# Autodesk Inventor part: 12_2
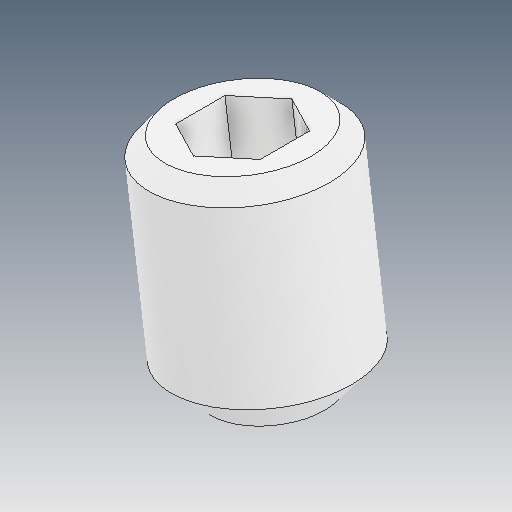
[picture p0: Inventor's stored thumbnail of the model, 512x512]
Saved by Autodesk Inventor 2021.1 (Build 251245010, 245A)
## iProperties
Created: 2021-06
Part Number: 12_2
Material: Ogólny
Document SubType Name: Modeling
Designer: user
Density: 1 g/cm^3
Appearance: Domyślna
Author: user
Revision Number: ÈÎºÎ
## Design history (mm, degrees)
feature "ÊäÈë1"
node "Bryła1"
